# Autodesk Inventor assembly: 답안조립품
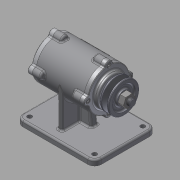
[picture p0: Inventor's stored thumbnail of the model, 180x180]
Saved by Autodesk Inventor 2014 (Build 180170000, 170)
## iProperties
Created: 2015-12
Part Number: 답안조립품
Document SubType Name: Assembly
Designer: USER
Author: USER
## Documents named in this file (11)
- C:\Users\USER\Desktop\451207V1026\답안조립품.iam
- C:\Users\USER\Desktop\451207V1026\본체.ipt
- C:\Users\USER\Desktop\451207V1026\V-벨트풀리.ipt
- C:\Users\USER\Desktop\451207V1026\너트 M12x1.25.ipt
- C:\Users\USER\Desktop\451207V1026\베어링 6204.ipt
- C:\Users\USER\Desktop\451207V1026\볼트 M4 x 12.ipt
- C:\Users\USER\Desktop\451207V1026\오일실.ipt
- C:\Users\USER\Desktop\451207V1026\축.ipt
- C:\Users\USER\Desktop\451207V1026\커버.ipt
- C:\Users\USER\Desktop\451207V1026\커버2.ipt
- C:\Users\USER\Desktop\451207V1026\키(4 x 4 x 12).ipt
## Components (6 placed, 5 different names)
1. V-벨트풀리:1
2. KS B 1012 클래스 1 일반 - 미터 M12x1.25:1
3. KS B 2023 6204 - 20 x 47 x 14:1
4. KS B 2804 D D - 20 32 8:1
5. KS B 1311 (I) 4 x 4 x 12:1
6. KS B 2023 6204 - 20 x 47 x 14:2
